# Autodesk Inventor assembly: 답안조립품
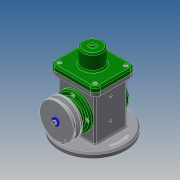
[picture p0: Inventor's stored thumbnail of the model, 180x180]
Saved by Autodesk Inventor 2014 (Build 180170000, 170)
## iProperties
Created: 2019-08
Part Number: 답안조립품
Document SubType Name: Assembly
Designer: kb542-15
Author: kb542-15
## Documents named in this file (18)
- C:\Users\kb542-15\Desktop\490804V1041\답안조립품.iam
- C:\Users\kb542-15\Desktop\490804V1041\본체.ipt
- C:\Users\kb542-15\Desktop\490804V1041\E-링.ipt
- C:\Users\kb542-15\Desktop\490804V1041\V-벨트풀리.ipt
- C:\Users\kb542-15\Desktop\490804V1041\덮개.ipt
- C:\Users\kb542-15\Desktop\490804V1041\뒤커버.ipt
- C:\Users\kb542-15\Desktop\490804V1041\링크.ipt
- C:\Users\kb542-15\Desktop\490804V1041\베어링 17 x 40 x 12.ipt
- C:\Users\kb542-15\Desktop\490804V1041\볼트 M4 x 8.ipt
- C:\Users\kb542-15\Desktop\490804V1041\볼트 M4 x 10.ipt
- C:\Users\kb542-15\Desktop\490804V1041\슬라이더.ipt
- C:\Users\kb542-15\Desktop\490804V1041\앞커버.ipt
- C:\Users\kb542-15\Desktop\490804V1041\오일 실 17 30 8.ipt
- C:\Users\kb542-15\Desktop\490804V1041\와셔 4x16.ipt
- C:\Users\kb542-15\Desktop\490804V1041\클레비스 핀 6 x 22.ipt
- 클레비스 핀 6 x 22.ipt
- C:\Users\kb542-15\Desktop\490804V1041\키 4 x 4 x 12.ipt
- C:\Users\kb542-15\Desktop\490804V1041\편심축.ipt
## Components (2 placed, 2 different names)
1. E-링:1
2. V-벨트풀리:1
